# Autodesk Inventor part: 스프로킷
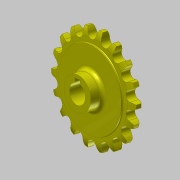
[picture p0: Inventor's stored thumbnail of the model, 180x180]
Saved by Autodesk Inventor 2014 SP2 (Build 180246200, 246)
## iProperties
Created: 2016-03
Part Number: 스프로킷
Material: 강철, 탄소
Document SubType Name: Modeling
Designer: mduedu
Density: 7.87 g/cm^3
Mass: 301.818 g
Surface Area: 124.882 cm^2
Volume: 38.3505 cm^3
Appearance: 매끄러움 - 노란색
Author: mduedu
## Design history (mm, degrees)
sketch "스케치1"
  geometry: L1 (0, 5)-(29.5, 5); L2 (29.5, 5)-(29.5, 4.1); L3 (30, 3.6)-(33.625, 3.6); L4 (40, 2)-(40, 0); L5 (40, 0)-(0, 0); L6 (0, 0)-(0, 5); L7 (0, -5)-(29.5, -5); L8 (29.5, -5)-(29.5, -4.1); L9 (30, -3.6)-(33.625, -3.6); L10 (40, -2)-(40, 0); L11 (0, 0)-(0, -5); A1 r 13.5 centre (33.625, -9.9) between (40, 2) and (33.625, 3.6); A2 r 13.5 centre (33.625, 9.9) between (33.625, -3.6) and (40, -2); A3 r 0.5 centre (30, 4.1) between (29.5, 4.1) and (30, 3.6); A4 r 0.5 centre (30, -4.1) between (30, -3.6) and (29.5, -4.1); 2 further points
  constraints: 22 end point, 8 point on circle, 6 symmetric about line, 5 tangent, 4 centre point, 4 parallel, 4 point on line, 1 equal radius, 1 horizontal, 1 perpendicular, 1 other
  dimensions: "d0" = 80 diameter of L4 L6; "d2" = 59 diameter of L2 L6; "d3" = 1.6 vertical distance of L4.start L3.end; "d4" = 3.6 distance from line of L4.end L3; "d5" = 5 distance between parallel lines of L5 L1; "d6" = 13.5 radius of A1; "d15" = 0.5 radius of A3
revolve "회전1" sketch "스케치1" stored, may be unused: angle "d7" = 90 deg
sketch "스케치2" dims "d8" = 65.2, "d11" = 80
  geometry: L1 (0, 0)-(0, 32.6); A1 r 36.57 centre (0, 0) between (-16.231, 32.771) and (0, 36.57); A2 r 3.97 centre (0, 36.57) between (-3.866, 35.665) and (0, 32.6); A3 r 12.7 centre (-16.231, 32.771) between (-3.866, 35.665) and (-5.534, 39.615); A4 r 12.7 centre (16.231, 32.771) between (5.534, 39.615) and (3.866, 35.665); A5 r 3.97 centre (0, 36.57) between (0, 32.6) and (3.866, 35.665); A6 r 40 centre (0, 0) between (5.534, 39.615) and (-5.534, 39.615); 2 further points
  constraints: 12 point on circle, 6 centre point, 4 coincident, 3 symmetric about line, 2 end point, 1 point on line, 1 tangent, 1 vertical, 1 vertical alignment, 7 other
  dimensions: "d10" = 73.14 diameter of A1; "d12" = 12.7 radius of A3
extrude "돌출1" cut sketch "스케치2" stored distance "d13" = 10; taper "d14" = 0 deg
sketch "스케치3"
  geometry: C1 r 12.5 at (0, 0); 1 further point
  constraints: 1 centre point, 1 coincident
  dimensions: "d19" = 25 diameter of C1
extrude "돌출2" join sketch "스케치3" distance "d20" = 10; taper "d21" = 0 deg
fillet "모깎기1" dims "d22" = 3
sketch "스케치4"
  geometry: L1 (-2.5, 0)-(2.5, 0); L2 (2.5, 0)-(2.5, 9.8); L3 (2.5, 9.8)-(-2.5, 9.8); L4 (-2.5, 9.8)-(-2.5, 0); C1 r 7.5 at (0, 0); 2 further points
  constraints: 8 end point, 2 coincident, 2 parallel, 1 centre point, 1 horizontal, 1 midpoint, 1 perpendicular
  dimensions: "d23" = 15 diameter of C1; "d25" = 5 distance of L2.end L3.end; "d26" = 9.8 distance of L1.end L2.end
extrude "돌출3" cut sketch "스케치4" stored distance "d27" = 8; taper "d28" = 0 deg
node "솔리드1"
pattern_circular "원형 패턴1" dims angle "d17" = 360 deg
